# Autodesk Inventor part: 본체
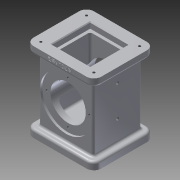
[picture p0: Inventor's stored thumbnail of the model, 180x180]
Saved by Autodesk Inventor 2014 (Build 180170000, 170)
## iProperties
Created: 2017-08
Part Number: 본체
Material: 알루미늄 6061
Document SubType Name: Modeling
Designer: 601-14
Density: 2.71 g/cm^3
Appearance: 알루미늄 - 평지
Mass: 872.531 g
Surface Area: 642.848 cm^2
Volume: 321.967 cm^3
Author: 601-14
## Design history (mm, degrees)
sketch "스케치1"
  geometry: L1 (46, 41)-(-46, 41); L2 (-46, 41)-(-46, -41); L3 (-46, -41)-(46, -41); L4 (46, -41)-(46, 41); L5 (46, 41)-(-46, -41); L6 (-46, 41)-(46, -41); 1 further point
  constraints: 12 end point, 2 midpoint, 2 parallel, 1 horizontal, 1 perpendicular
  dimensions: "d0" = 82 distance of L3.end L1.start; "d1" = 92 distance between parallel lines of L4 L2
extrude "돌출1" new body sketch "스케치1" distance "d2" = 10; taper "d3" = 0 deg
sketch "스케치2"
  geometry: L1 (37, 33)-(-37, 33); L2 (-37, 33)-(-37, -33); L3 (-37, -33)-(37, -33); L4 (37, -33)-(37, 33); L5 (37, 33)-(-37, -33); L6 (-37, 33)-(37, -33); 1 further point
  constraints: 12 end point, 2 midpoint, 2 parallel, 1 horizontal, 1 perpendicular
  dimensions: "d4" = 74 distance between parallel lines of L4 L2; "d5" = 66 distance between parallel lines of L3 L1
extrude "돌출2" join sketch "스케치2" distance "d6" = 88; taper "d7" = 0 deg
sketch "스케치3"
  geometry: L1 (46, 41)-(-46, 41); L2 (-46, 41)-(-46, -41); L3 (-46, -41)-(46, -41); L4 (46, -41)-(46, 41); L5 (46, 41)-(-46, -41); L6 (-46, 41)-(46, -41); 1 further point
  constraints: 12 end point, 2 midpoint, 2 parallel, 1 horizontal, 1 perpendicular
  dimensions: "d8" = 92 distance between parallel lines of L4 L2; "d9" = 82 distance between parallel lines of L3 L1
extrude "돌출3" join sketch "스케치3" distance "d10" = 10; taper "d11" = 0 deg
sketch "스케치5"
  geometry: L1 (-9, -10)-(83, -10) reference; C1 r 35 at (37, 44); 1 further point
  constraints: 1 centre point
  dimensions: "d12" = 70 diameter of C1; "d13" = 54 distance from line of L1 C1.centre
extrude "돌출4" cut sketch "스케치5" distance "d14" = 3; taper "d15" = 0 deg
sketch "스케치6"
  geometry: L1 (83, 10)-(-9, 10) reference; C1 r 35 at (37, -44); 1 further point
  constraints: 1 centre point
  dimensions: "d16" = 70 diameter of C1; "d17" = 54 distance from line of L1 C1.centre
extrude "돌출5" cut sketch "스케치6" distance "d18" = 3; taper "d19" = 0 deg
sketch "스케치7"
  geometry: C1 r 35 at (0, 0) reference; C2 r 24 at (0, 0); 1 further point
  constraints: 1 centre point, 1 coincident
  dimensions: "d20" = 48 diameter of C2
extrude "돌출6" cut sketch "스케치7" distance "d21" = 68; taper "d22" = 0 deg
sketch "스케치8" dims "d23" = 58
  geometry: L1 (0, 0)-(0, 54.477); C1 r 35 at (0, 0) reference; 2 further points
  constraints: 2 end point, 1 coincident, 1 point on line, 1 vertical, 1 vertical alignment, 2 other
hole "구멍1" sketch "스케치8" at (0, 29) diameter "d24" = 3.242; stored, may be unused: countersink angle "d28" = 90 deg, drill point angle "d30" = 118 deg; dims "d25" = 4, "d26" = 4, "d27" = 2, "d29" = 6
node "작업 평면1"
sketch "스케치9"
  geometry: L1 (26, 26)-(-26, 26); L2 (-26, 26)-(-26, -26); L3 (-26, -26)-(26, -26); L4 (26, -26)-(26, 26); L5 (26, 26)-(-26, -26); L6 (-26, 26)-(26, -26); 1 further point
  constraints: 12 end point, 2 midpoint, 2 parallel, 1 horizontal, 1 perpendicular
  dimensions: "d34" = 52 distance between parallel lines of L3 L1; "d35" = 52 distance between parallel lines of L4 L2
extrude "돌출7" cut sketch "스케치9" distance "d36" = 8; taper "d37" = 0 deg
sketch "스케치10"
  geometry: L1 (24, 24)-(-24, 24); L2 (-24, 24)-(-24, -24); L3 (-24, -24)-(24, -24); L4 (24, -24)-(24, 24); L5 (24, 24)-(-24, -24); L6 (-24, 24)-(24, -24); 1 further point
  constraints: 12 end point, 2 midpoint, 2 parallel, 1 horizontal, 1 perpendicular
  dimensions: "d38" = 48 distance between parallel lines of L3 L1; "d39" = 48 distance between parallel lines of L2 L4
extrude "돌출8" cut sketch "스케치10" distance "d40" = 16; taper "d41" = 0 deg
sketch "스케치11"
  geometry: L1 (22, 22)-(-22, 22); L2 (-22, 22)-(-22, -22); L3 (-22, -22)-(22, -22); L4 (22, -22)-(22, 22); L5 (22, 22)-(-22, -22); L6 (-22, 22)-(22, -22); 1 further point
  constraints: 12 end point, 2 midpoint, 2 parallel, 1 horizontal, 1 perpendicular
  dimensions: "d42" = 44 distance between parallel lines of L3 L1; "d43" = 44 distance between parallel lines of L2 L4
extrude "돌출9" cut sketch "스케치11" distance "d44" = 74; taper "d45" = 0 deg
sketch "스케치12"
  geometry: L1 (0, 66)-(0, 0) reference; L2 (-88, 0)-(-88, 66) reference; L3 (-88, 33)-(0, 33); L4 (10, -8)-(10, 74) reference; 3 further points
  constraints: 2 end point, 2 midpoint, 2 point on line
  dimensions: "d46" = 38 distance from line of L4 point (-28, 33); "d47" = 42 distance of point (-28, 33) point (-70, 33)
hole "구멍2" sketch "스케치12" at (-28, 33), (-70, 33) diameter "d48" = 4.134; stored, may be unused: countersink angle "d52" = 90 deg, drill point angle "d54" = 118 deg; dims "d49" = 20, "d50" = 4, "d51" = 2, "d53" = 20
sketch "스케치13"
  geometry: L1 (36, 31)-(-36, 31); L2 (-36, 31)-(-36, -31); L3 (-36, -31)-(36, -31); L4 (36, -31)-(36, 31); L5 (36, 31)-(-36, -31); L6 (-36, 31)-(36, -31); 5 further points
  constraints: 12 end point, 4 coincident, 2 midpoint, 2 parallel, 1 horizontal, 1 perpendicular
  dimensions: "d55" = 72 distance between parallel lines of L4 L2; "d56" = 62 distance between parallel lines of L3 L1
hole "구멍3" sketch "스케치13" at (-36, 31), (-36, -31), (36, 31), (36, -31) diameter "d57" = 3.242; stored, may be unused: countersink angle "d61" = 90 deg, drill point angle "d63" = 118 deg; dims "d58" = 4, "d59" = 4, "d60" = 2, "d62" = 6
node "작업 평면2"
sketch "스케치14"
  geometry: L1 (0, 10)-(92, 10) reference; L2 (0, 0)-(0, 10) reference; 2 further points
  constraints: 1 other
  dimensions: "d65" = 4 distance from line of point (46, 6) L1; "d66" = 46 distance from line of point (46, 6) L2
feature "엠보싱1" sketch "스케치14" dims "d0" = 82, "d1" = 92, "d67" = 0.5, "d68" = 0
fillet "모깎기1" dims "d69" = 10
fillet "모깎기2" dims "d70" = 3
fillet "모깎기3" dims "d71" = 3
fillet "모깎기4" dims "d72" = 3
fillet "모깎기5" dims "d73" = 3
fillet "모깎기6" dims "d74" = 3
fillet "모깎기7" dims "d75" = 3
fillet "모깎기8" dims "d76" = 3
chamfer "모따기2" distance "d80" = 1; stored, may be unused: second distance "d81" = 2, angle "d82" = 45 deg
node "솔리드1"
pattern_circular "원형 패턴1" dims angle "d32" = 360 deg
mirror "대칭1"
mirror "대칭2"
